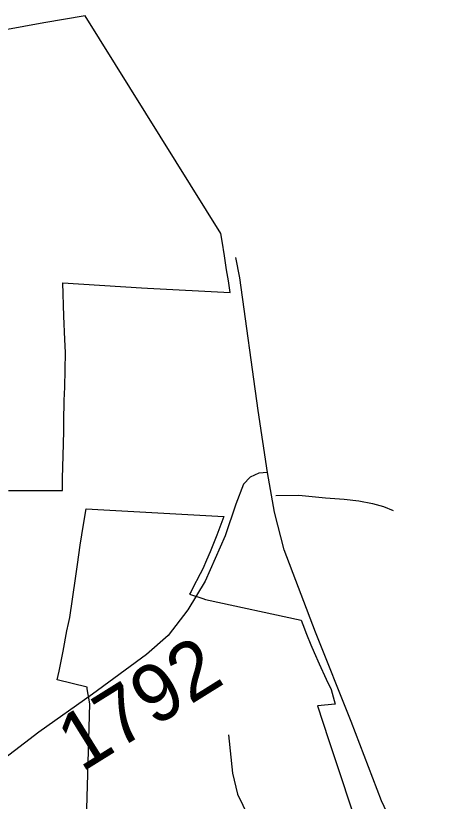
# Model space of a CAD drawing. Extents: x 2001466 to 31450019, y -30647475 to 847247.
# Drawn here: x 31440417 to 31442235, y -30621416 to -30618000 of the extents above; entities that cross this region are included whole.
import ezdxf

# ---------------------------------------------------------------- set-up
doc = ezdxf.new("R2010")
doc.units = 0
for name, color, linetype in [('Exist Boundary Political City Limit New', 7, 'Continuous'), ('Exist Road Non-System Type 51', 7, 'Continuous'), ('Exist Road Secondary Type 51 Attributed', 7, 'Continuous'), ('Exist Road Secondary Type 51 Number Label', 7, 'Continuous'), ('Map Preparation Boundary City Limit Buffer Line', 7, 'Continuous')]:
    doc.layers.add(name, color=color, linetype=linetype)

msp = doc.modelspace()

# ---------------------------------------------------------------- linework, layer by layer
at = {"layer": 'Exist Boundary Political City Limit New'}
msp.add_line((31441309.6, -30618947.2), (31440719.7, -30618000.2), dxfattribs=at)
for points in [[(31440719.7, -30618000.2), (31440539.5, -30618031.6), (31440365.1, -30618063.3)], [(31440385.8, -30620064.9), (31440423.9, -30620065), (31440620.6, -30620064.9), (31440621.5, -30620011.3), (31440623.9, -30619914.1), (31440626.5, -30619806.7), (31440627.4, -30619764.8), (31440629.1, -30619673.3), (31440630.6, -30619615.5), (31440634.3, -30619465), (31440630.8, -30619408.1), (31440626.8, -30619307), (31440622.5, -30619161.8), (31440964.8, -30619183.8), (31440991.5, -30619185.7), (31441350.8, -30619203.8), (31441344.1, -30619153.3), (31441335.4, -30619105), (31441326.4, -30619044.8), (31441316.6, -30618981.1), (31441309.6, -30618947.2)], [(31440723.5, -30621548.6), (31440735.3, -30621147.8), (31440739.8, -30620992.1), (31440728, -30620926.9), (31440729.1, -30620920.6), (31440597.8, -30620888.5), (31440606.8, -30620850.4), (31440623.4, -30620764.1), (31440640.4, -30620675.6), (31440647.8, -30620642.6), (31440653.4, -30620617.2), (31440677.9, -30620448), (31440686.5, -30620386.7), (31440698.4, -30620302.5), (31440712.6, -30620213.4), (31440723.6, -30620144.6), (31440801.4, -30620148.6), (31441324.1, -30620178.5), (31441292.9, -30620258.6), (31441263.6, -30620331.6), (31441248.5, -30620367.7), (31441231.4, -30620406), (31441221, -30620427.7), (31441187.6, -30620491.5), (31441180.5, -30620504.2), (31441173.9, -30620515.1), (31441232.1, -30620534.8), (31441244.1, -30620538.2), (31441659.4, -30620628.5), (31441666.9, -30620648), (31441683.5, -30620690.2), (31441702, -30620735.5)], [(31441702, -30620735.5), (31441716.6, -30620769), (31441737.8, -30620818.7), (31441768.4, -30620884.6), (31441790, -30620930.5), (31441807.5, -30620993.8), (31441731.4, -30621001.7), (31441779.5, -30621147.8), (31441833.9, -30621313.3), (31441905.3, -30621529)]]:
    msp.add_lwpolyline(points, dxfattribs=at)
at = {"layer": 'Exist Road Non-System Type 51'}
for points in [[(31441549.8, -30620086.8), (31441649.9, -30620084.8), (31441765.6, -30620097.2), (31441847.5, -30620102.8), (31441911.3, -30620110.1), (31441971.1, -30620121.4), (31442018.9, -30620134.3), (31442060.2, -30620152.2)], [(31441344.4, -30621128.1), (31441361.8, -30621294.2), (31441383, -30621385), (31441429.3, -30621481.6), (31441514.3, -30621578.2), (31441605, -30621641.9), (31441715, -30621676.7), (31441821.2, -30621682.5), (31441954.4, -30621663.2), (31442107.5, -30621621.9)]]:
    msp.add_lwpolyline(points, dxfattribs=at)
at = {"layer": 'Exist Road Secondary Type 51 Attributed'}
for points in [[(31441513, -30619987), (31441472.7, -30619716.4), (31441393.1, -30619139.8), (31441375, -30619052.3)], [(31441513, -30619987), (31441475.9, -30619990.2), (31441437.3, -30620006.3), (31441408.4, -30620036.9), (31441376.2, -30620123.9), (31441329.5, -30620262.4), (31441242.6, -30620458.9), (31441166.5, -30620584.5), (31441080.4, -30620694.8), (31440987.1, -30620778.6), (31440752.1, -30620950.9), (31440517.5, -30621115.2), (31440348.9, -30621244.1)], [(31442364.4, -30622265.3), (31442271, -30622024.3), (31442174.5, -30621765), (31442010.3, -30621413.9), (31441878.3, -30621069.3), (31441723, -30620681.1), (31441586.2, -30620323.6), (31441544.4, -30620159.3), (31441513, -30619987)]]:
    msp.add_lwpolyline(points, dxfattribs=at)
at = {"layer": 'Map Preparation Boundary City Limit Buffer Line'}
msp.add_line((31441309.6, -30618947.2), (31440719.7, -30618000.2), dxfattribs=at)
for points in [[(31440719.7, -30618000.2), (31440539.5, -30618031.6), (31440365.1, -30618063.3)], [(31440385.8, -30620064.9), (31440423.9, -30620065), (31440620.6, -30620064.9), (31440621.5, -30620011.3), (31440623.9, -30619914.1), (31440626.5, -30619806.7), (31440627.4, -30619764.8), (31440629.1, -30619673.3), (31440630.6, -30619615.5), (31440634.3, -30619465), (31440630.8, -30619408.1), (31440626.8, -30619307), (31440622.5, -30619161.8), (31440964.8, -30619183.8), (31440991.5, -30619185.7), (31441350.8, -30619203.8), (31441344.1, -30619153.3), (31441335.4, -30619105), (31441326.4, -30619044.8), (31441316.6, -30618981.1), (31441309.6, -30618947.2)], [(31440723.5, -30621548.6), (31440735.3, -30621147.8), (31440739.8, -30620992.1), (31440728, -30620926.9), (31440729.1, -30620920.6), (31440597.8, -30620888.5), (31440606.8, -30620850.4), (31440623.4, -30620764.1), (31440640.4, -30620675.6), (31440647.8, -30620642.6), (31440653.4, -30620617.2), (31440677.9, -30620448), (31440686.5, -30620386.7), (31440698.4, -30620302.5), (31440712.6, -30620213.4), (31440723.6, -30620144.6), (31440801.4, -30620148.6), (31441324.1, -30620178.5), (31441292.9, -30620258.6), (31441263.6, -30620331.6), (31441248.5, -30620367.7), (31441231.4, -30620406), (31441221, -30620427.7), (31441187.6, -30620491.5), (31441180.5, -30620504.2), (31441173.9, -30620515.1), (31441232.1, -30620534.8), (31441244.1, -30620538.2), (31441659.4, -30620628.5), (31441666.9, -30620648), (31441683.5, -30620690.2), (31441702, -30620735.5)], [(31441702, -30620735.5), (31441716.6, -30620769), (31441737.8, -30620818.7), (31441768.4, -30620884.6), (31441790, -30620930.5), (31441807.5, -30620993.8), (31441731.4, -30621001.7), (31441779.5, -30621147.8), (31441833.9, -30621313.3), (31441905.3, -30621529)]]:
    msp.add_lwpolyline(points, dxfattribs=at)

# ---------------------------------------------------------------- texts
at = {"layer": 'Exist Road Secondary Type 51 Number Label'}
msp.add_text('1792', height=250, rotation=31.918, dxfattribs=at).set_placement((31440703.6, -30621292.8))

doc.saveas('drawing.dxf')
